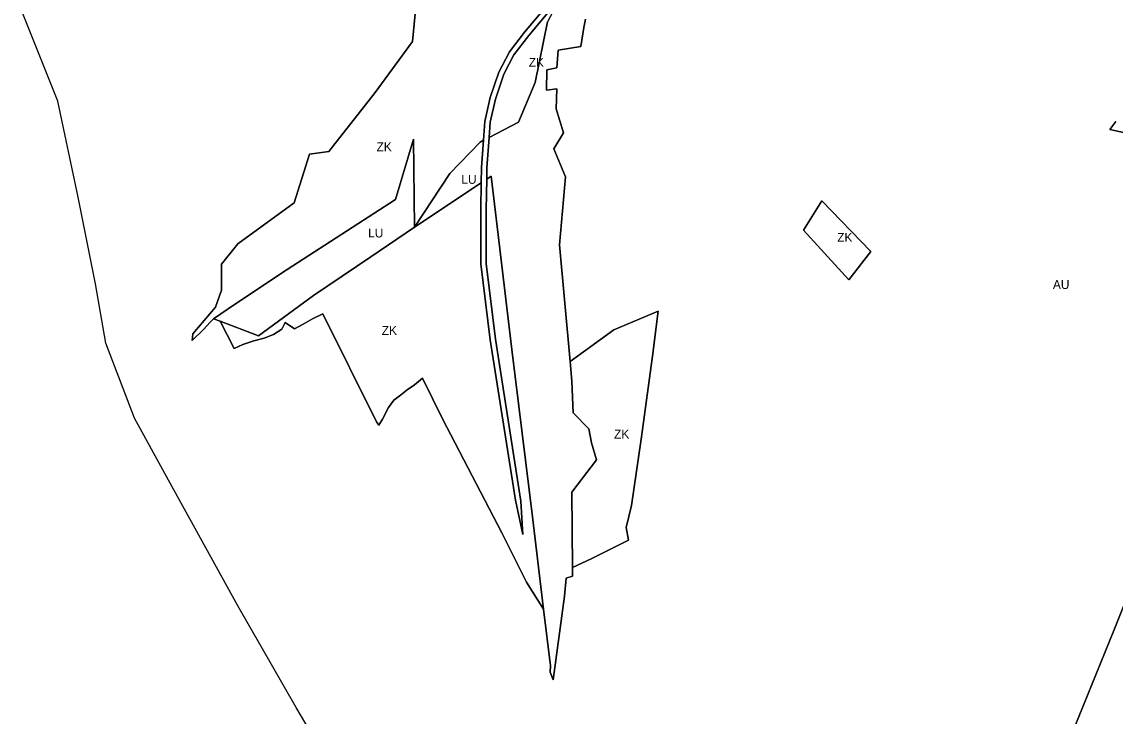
# Model space of a CAD drawing. Extents: x -532067 to -529270, y -1180561 to -1176456.
# Drawn here: x -531324 to -530711, y -1179375 to -1178985 of the extents above; entities that cross this region are included whole.
import ezdxf

# ---------------------------------------------------------------- set-up
doc = ezdxf.new("R2010")
doc.units = 0
for name, color, linetype in [('90630013', 7, 'Continuous'), ('90710013', 7, 'Continuous'), ('90750013', 7, 'Continuous'), ('90770013', 7, 'Continuous')]:
    doc.layers.add(name, color=color, linetype=linetype)

msp = doc.modelspace()

# ---------------------------------------------------------------- linework, layer by layer
at = {"layer": '90630013'}
msp.add_lwpolyline([(-531025.4723, -1178975.76945), (-531039.9043, -1178993.05145), (-531048.2503, -1179003.84145), (-531053.9213, -1179014.79845), (-531058.6293, -1179028.66145), (-531061.5003, -1179041.71745), (-531062.1193, -1179050.21345), (-531063.3583, -1179067.21245), (-531063.5033, -1179073.63745), (-531063.8883, -1179090.63545), (-531063.8883, -1179121.03245), (-531058.5473, -1179163.50745), (-531044.3773, -1179254.38445), (-531043.2443, -1179273.16445), (-531047.4163, -1179253.90745), (-531061.5183, -1179163.92745), (-531066.8883, -1179121.22045), (-531066.8883, -1179090.60145), (-531066.5503, -1179075.66745), (-531066.3563, -1179067.06945), (-531065.2463, -1179051.84345), (-531064.4763, -1179041.28445), (-531061.5233, -1179027.85445), (-531056.6893, -1179013.61945), (-531050.7893, -1179002.22145), (-531042.2433, -1178991.17145), (-531027.9663, -1178974.07545)], dxfattribs=at)
at = {"layer": '90710013'}
for points in [[(-531045.6303, -1179041.61945), (-531062.1193, -1179050.21345), (-531061.5003, -1179041.71745), (-531058.6293, -1179028.66145), (-531053.9213, -1179014.79845), (-531048.2503, -1179003.84145), (-531039.9043, -1178993.05145), (-531025.4723, -1178975.76945), (-531019.1183, -1178964.07745), (-531018.7193, -1178963.20145), (-531017.7253, -1178963.35045), (-531029.3253, -1178985.34245), (-531036.2273, -1179019.31245)], [(-531104.0743, -1179100.66545), (-531066.5503, -1179075.66745), (-531066.8883, -1179090.60145), (-531066.8883, -1179121.22045), (-531061.5183, -1179163.92745), (-531047.4163, -1179253.90745), (-531043.2443, -1179273.16445), (-531044.3773, -1179254.38445), (-531058.5473, -1179163.50745), (-531063.8883, -1179121.03245), (-531063.8883, -1179090.63545), (-531063.5033, -1179073.63745), (-531061.0463, -1179072.00045), (-531049.4773, -1179169.35045), (-531037.8153, -1179263.12745), (-531031.5953, -1179315.04845), (-531041.2183, -1179299.84045), (-531054.9363, -1179272.14445), (-531088.3533, -1179208.27045), (-531099.6283, -1179185.28745), (-531103.9923, -1179189.11845), (-531108.1743, -1179191.85445), (-531111.8113, -1179194.95445), (-531115.6303, -1179197.69145), (-531118.5393, -1179201.88645), (-531121.9943, -1179208.45245), (-531123.9943, -1179211.73545), (-531125.3113, -1179209.83545), (-531155.5253, -1179149.22145), (-531161.2803, -1179152.10845), (-531166.5553, -1179154.99445), (-531171.3513, -1179157.64045), (-531176.6263, -1179154.03245), (-531178.5453, -1179157.88045), (-531183.1013, -1179160.76745), (-531188.3763, -1179162.93245), (-531194.1313, -1179164.37545), (-531200.3663, -1179166.54045), (-531205.1623, -1179168.70445), (-531213.1783, -1179153.36345), (-531191.6573, -1179161.61745), (-531160.6413, -1179138.97245), (-531128.5713, -1179117.17345)], [(-530847.8523, -1179114.18645), (-530860.2313, -1179130.15245), (-530885.7473, -1179102.27545), (-530875.3893, -1179085.80245)], [(-531004.4833, -1179286.66745), (-531015.2793, -1179291.70545), (-531015.7823, -1179249.38945), (-531001.9723, -1179231.25345), (-531004.7343, -1179221.68245), (-531006.2403, -1179213.87345), (-531015.0283, -1179204.80645), (-531015.7483, -1179187.08645), (-531016.6973, -1179175.98045), (-530992.1533, -1179158.19145), (-530967.3553, -1179147.74245), (-530970.5183, -1179173.06145), (-530976.8443, -1179219.70345), (-530982.2213, -1179256.82645), (-530985.1493, -1179269.28745), (-530983.8933, -1179276.34045), (-530987.6603, -1179278.10345), (-530998.4563, -1179283.64445)]]:
    msp.add_lwpolyline(points, close=True, dxfattribs=at)
msp.add_lwpolyline([(-531027.9663, -1178974.07545), (-531042.2433, -1178991.17145), (-531050.7893, -1179002.22145), (-531056.6893, -1179013.61945), (-531061.5233, -1179027.85445), (-531064.4763, -1179041.28445), (-531065.2463, -1179051.84345), (-531067.1513, -1179052.83645), (-531084.2413, -1179070.40245), (-531104.0743, -1179100.66545), (-531104.6033, -1179051.12945), (-531114.6723, -1179085.13745), (-531175.4113, -1179124.36945), (-531204.5273, -1179143.62845), (-531216.7653, -1179152.09445), (-531218.6643, -1179153.99845), (-531222.4623, -1179158.02045), (-531228.8523, -1179164.29845), (-531228.3693, -1179160.55945), (-531215.7103, -1179145.53345), (-531212.3343, -1179136.00945), (-531212.3343, -1179121.40645), (-531203.2613, -1179109.97745), (-531171.5883, -1179086.99245), (-531162.9583, -1179059.58045), (-531152.0213, -1179058.18745), (-531126.1043, -1179025.00645), (-531105.1903, -1178996.29345), (-531102.0663, -1178965.19545)], dxfattribs=at)
at = {"layer": '90750013'}
for points in [[(-531102.0663, -1178965.19545), (-531105.1903, -1178996.29345), (-531126.1043, -1179025.00645), (-531152.0213, -1179058.18745), (-531162.9583, -1179059.58045), (-531171.5883, -1179086.99245), (-531203.2613, -1179109.97745), (-531212.3343, -1179121.40645), (-531212.3343, -1179136.00945), (-531215.7103, -1179145.53345), (-531228.3693, -1179160.55945), (-531228.8523, -1179164.29845), (-531222.4623, -1179158.02045), (-531218.6643, -1179153.99845), (-531216.7653, -1179152.09445), (-531213.1783, -1179153.36345), (-531205.1623, -1179168.70445), (-531200.3663, -1179166.54045), (-531194.1313, -1179164.37545), (-531188.3763, -1179162.93245), (-531183.1013, -1179160.76745), (-531178.5453, -1179157.88045), (-531176.6263, -1179154.03245), (-531171.3513, -1179157.64045), (-531166.5553, -1179154.99445), (-531161.2803, -1179152.10845), (-531155.5253, -1179149.22145), (-531125.3113, -1179209.83545), (-531123.9943, -1179211.73545), (-531121.9943, -1179208.45245), (-531118.5393, -1179201.88645), (-531115.6303, -1179197.69145), (-531111.8113, -1179194.95445), (-531108.1743, -1179191.85445), (-531103.9923, -1179189.11845), (-531099.6283, -1179185.28745), (-531088.3533, -1179208.27045), (-531054.9363, -1179272.14445), (-531041.2183, -1179299.84045), (-531031.5953, -1179315.04845), (-531027.6953, -1179346.85045), (-531027.9343, -1179350.44745), (-531026.2603, -1179354.76445), (-531019.8023, -1179307.72745), (-531018.8473, -1179297.67245), (-531015.2683, -1179296.47545), (-531015.2793, -1179291.70545), (-531004.4833, -1179286.66745), (-530998.4563, -1179283.64445), (-530987.6603, -1179278.10345), (-530983.8933, -1179276.34045), (-530985.1493, -1179269.28745), (-530982.2213, -1179256.82645), (-530976.8443, -1179219.70345), (-530970.5183, -1179173.06145), (-530967.3553, -1179147.74245), (-530992.1533, -1179158.19145), (-531016.6973, -1179175.98045), (-531022.6063, -1179110.49345), (-531019.2943, -1179072.28945), (-531025.8403, -1179056.70745), (-531020.4723, -1179047.66145), (-531024.5523, -1179034.09145), (-531024.1223, -1179022.89045), (-531029.9903, -1179023.62045), (-531029.8043, -1179012.27145), (-531024.0553, -1179011.15445), (-531023.3133, -1179001.29345), (-531010.7013, -1178999.24745), (-531009.0323, -1178988.45645), (-531008.1043, -1178983.80445)], [(-531143.7973, -1179415.14145), (-531170.5143, -1179370.32245), (-531203.2523, -1179313.10545), (-531242.0643, -1179242.68445), (-531261.1083, -1179207.74645), (-531277.2813, -1179165.72345), (-531283.1133, -1179132.47845), (-531292.8583, -1179083.76045), (-531304.2533, -1179029.90345), (-531324.3793, -1178979.33545)], [(-530710.4553, -1179041.28045), (-530713.8673, -1179045.84445), (-530638.6183, -1179062.40745)], [(-530692.4043, -1179279.29745), (-530711.6183, -1179327.08245), (-530752.8893, -1179428.87345), (-530780.3383, -1179501.33545), (-530792.0203, -1179529.85045), (-530840.3343, -1179531.93145), (-530866.4173, -1179584.85745), (-530883.0153, -1179626.18745), (-530904.8823, -1179682.75545), (-530925.0953, -1179729.23645), (-530887.7793, -1179774.78045), (-530821.6083, -1179839.30245), (-530802.5813, -1179881.01145), (-530784.2593, -1179922.01445), (-530738.3333, -1179952.54645), (-530710.5303, -1179971.53645)]]:
    msp.add_lwpolyline(points, dxfattribs=at)
msp.add_lwpolyline([(-530847.8523, -1179114.18645), (-530875.3893, -1179085.80245), (-530885.7473, -1179102.27545), (-530860.2313, -1179130.15245)], close=True, dxfattribs=at)
at = {"layer": '90770013'}
for points in [[(-531008.1043, -1178983.80445), (-531009.0323, -1178988.45645), (-531010.7013, -1178999.24745), (-531023.3133, -1179001.29345), (-531024.0553, -1179011.15445), (-531029.8043, -1179012.27145), (-531029.9903, -1179023.62045), (-531024.1223, -1179022.89045), (-531024.5523, -1179034.09145), (-531020.4723, -1179047.66145), (-531025.8403, -1179056.70745), (-531019.2943, -1179072.28945), (-531022.6063, -1179110.49345), (-531016.6973, -1179175.98045), (-531015.7483, -1179187.08645), (-531015.0283, -1179204.80645), (-531006.2403, -1179213.87345), (-531004.7343, -1179221.68245), (-531001.9723, -1179231.25345), (-531015.7823, -1179249.38945), (-531015.2793, -1179291.70545), (-531015.2683, -1179296.47545), (-531018.8473, -1179297.67245), (-531019.8023, -1179307.72745), (-531026.2603, -1179354.76445), (-531027.9343, -1179350.44745), (-531027.6953, -1179346.85045), (-531031.5953, -1179315.04845), (-531037.8153, -1179263.12745), (-531049.4773, -1179169.35045), (-531061.0463, -1179072.00045), (-531063.5033, -1179073.63745), (-531063.3583, -1179067.21245), (-531062.1193, -1179050.21345), (-531045.6303, -1179041.61945), (-531036.2273, -1179019.31245), (-531029.3253, -1178985.34245)], [(-530638.6183, -1179062.40745), (-530713.8673, -1179045.84445), (-530710.4553, -1179041.28045)], [(-530710.5303, -1179971.53645), (-530738.3333, -1179952.54645), (-530784.2593, -1179922.01445), (-530802.5813, -1179881.01145), (-530821.6083, -1179839.30245), (-530887.7793, -1179774.78045), (-530925.0953, -1179729.23645), (-530904.8823, -1179682.75545), (-530883.0153, -1179626.18745), (-530866.4173, -1179584.85745), (-530840.3343, -1179531.93145), (-530792.0203, -1179529.85045), (-530780.3383, -1179501.33545), (-530752.8893, -1179428.87345), (-530711.6183, -1179327.08245), (-530692.4043, -1179279.29745)]]:
    msp.add_lwpolyline(points, dxfattribs=at)
for points in [[(-531104.0743, -1179100.66545), (-531128.5713, -1179117.17345), (-531160.6413, -1179138.97245), (-531191.6573, -1179161.61745), (-531213.1783, -1179153.36345), (-531216.7653, -1179152.09445), (-531204.5273, -1179143.62845), (-531175.4113, -1179124.36945), (-531114.6723, -1179085.13745), (-531104.6033, -1179051.12945)], [(-531104.0743, -1179100.66545), (-531084.2413, -1179070.40245), (-531067.1513, -1179052.83645), (-531065.2463, -1179051.84345), (-531066.3563, -1179067.06945), (-531066.5503, -1179075.66745)]]:
    msp.add_lwpolyline(points, close=True, dxfattribs=at)

# ---------------------------------------------------------------- texts
at = {"layer": '90710013'}
for rotation, p in [(0.00000001, (-531039.9223, -1179010.57646)), (359.99999999, (-531125.3283, -1179057.98068)), (0.00000003, (-530866.7998, -1179108.81616)), (0.00000001, (-531122.3868, -1179161.05129)), (0.00000002, (-530992.0263, -1179219.24111))]:
    msp.add_text('ZK', height=5, rotation=rotation, dxfattribs=at).set_placement(p)
at = {"layer": '90750013'}
msp.add_text('AU', height=5, rotation=0.00000004, dxfattribs=at).set_placement((-530745.7408, -1179135.29234))
at = {"layer": '90770013'}
for rotation, p in [(359.99999997, (-531077.75393, -1179076.25445)), (0.00000001, (-531130.04728, -1179106.37345))]:
    msp.add_text('LU', height=5, rotation=rotation, dxfattribs=at).set_placement(p)

doc.saveas('drawing.dxf')
